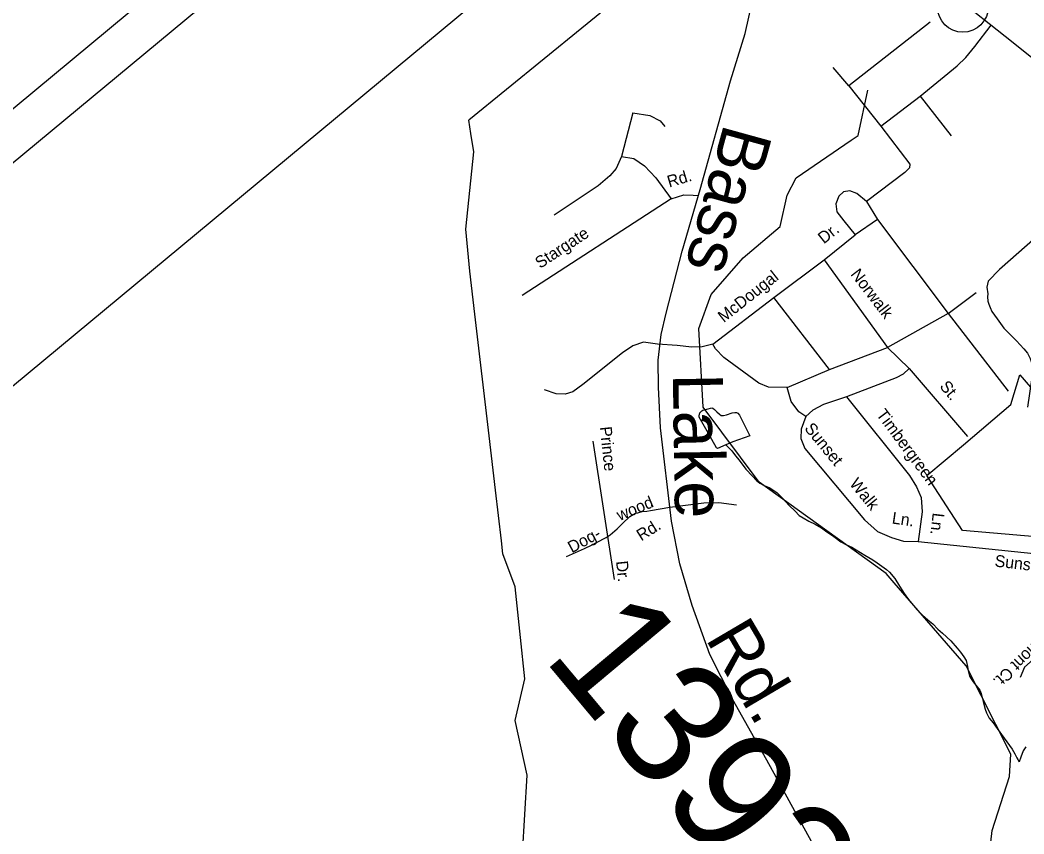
# Model space of a CAD drawing. Extents: x 2054826 to 2060231, y 685508 to 690809.
# Drawn here: x 2058521.5 to 2058702.3, y 689675 to 689821.4 of the extents above; entities that cross this region are included whole.
import ezdxf

# ---------------------------------------------------------------- set-up
doc = ezdxf.new("R2010")
doc.units = 0
for name, color, linetype in [('Default', 7, 'Continuous'), ('Old_Level_10', 7, 'Continuous'), ('Old_Level_11', 7, 'Continuous'), ('Old_Level_32', 7, 'Continuous'), ('Old_Level_35', 7, 'Continuous'), ('Old_Level_48', 7, 'Continuous'), ('Old_Level_49', 7, 'Continuous'), ('Old_Level_56', 7, 'Continuous'), ('Old_Level_59', 7, 'Continuous'), ('Old_Level_62', 7, 'Continuous'), ('Old_Level_8', 7, 'Continuous'), ('Sheet Title CELL', 7, 'Continuous')]:
    doc.layers.add(name, color=color, linetype=linetype)

msp = doc.modelspace()

# ---------------------------------------------------------------- linework, layer by layer
at = {"layer": 'Default'}
msp.add_lwpolyline([(2058776.37, 689968.05), (2059134.67, 689535.97), (2058721.62, 689193.45), (2058363.32, 689625.52)], close=True, dxfattribs=at)
msp.add_circle((2058691.27, 689823.81), 4.59, dxfattribs=at)
at = {"layer": 'Old_Level_32'}
for points in [[(2058898.06, 689750.93), (2058894.95, 689750.93), (2058888.19, 689750.36), (2058876.56, 689749.59), (2058861.91, 689747.84), (2058857.42, 689747.89), (2058845.09, 689749.43), (2058833.63, 689751.66), (2058828.28, 689753), (2058821.63, 689755.93), (2058816.8, 689757.3), (2058812.24, 689757.5), (2058808.13, 689757.14), (2058797.44, 689755.69), (2058792.44, 689755.38), (2058787.43, 689756.01), (2058779.61, 689758.56), (2058771.71, 689762.05), (2058763.67, 689767.02), (2058755.45, 689773.25), (2058734.54, 689789.73), (2058719.88, 689801.66), (2058700.32, 689817.33), (2058689.1, 689826.26)], [(2058679.59, 689634.33), (2058678.7, 689638.67), (2058676.93, 689646.07), (2058675.26, 689651.03), (2058672.43, 689657.49), (2058665.7, 689670.57), (2058655.97, 689688.24), (2058649.78, 689699.24), (2058645.72, 689707.22), (2058642.52, 689716.04), (2058640.32, 689723.55), (2058638.82, 689731.26), (2058636.85, 689748.06), (2058636.51, 689755.34), (2058636.4, 689760.19), (2058636.96, 689764.8), (2058637.85, 689768.69), (2058640.76, 689779.82), (2058643.98, 689790.93), (2058649.46, 689810.49), (2058652.07, 689818.96), (2058653.3, 689824.33)]]:
    msp.add_lwpolyline(points, dxfattribs=at)
at = {"layer": 'Old_Level_35'}
for p, q in [((2058685.41, 689821.03), (2058670.75, 689809.58)), ((2058670.75, 689809.58), (2058667.91, 689812.85)), ((2058670.75, 689809.58), (2058676.53, 689802.3)), ((2058676.53, 689802.3), (2058683.61, 689807.72)), ((2058683.61, 689807.72), (2058689.19, 689800.57)), ((2058631.88, 689804.7), (2058629.81, 689796.88)), ((2058638.75, 689789.24), (2058611.92, 689771.82)), ((2058673.94, 689788.73), (2058675.91, 689785.53)), ((2058675.91, 689785.53), (2058671.87, 689782.76)), ((2058675.91, 689785.53), (2058688.65, 689768.6)), ((2058666.29, 689778.29), (2058671.87, 689782.76)), ((2058657.22, 689771.51), (2058666.29, 689778.29)), ((2058666.29, 689778.29), (2058677.72, 689762.48)), ((2058688.65, 689768.6), (2058693.67, 689772.39)), ((2058646.29, 689763.08), (2058657.22, 689771.51)), ((2058667.25, 689758.55), (2058657.22, 689771.51)), ((2058688.65, 689768.6), (2058677.72, 689762.48)), ((2058688.65, 689768.6), (2058699.42, 689754.64)), ((2058667.25, 689758.55), (2058677.72, 689762.48)), ((2058677.72, 689762.48), (2058681.6, 689758.71)), ((2058659.65, 689755.32), (2058667.25, 689758.55)), ((2058681.6, 689758.71), (2058692.11, 689746.5)), ((2058624.64, 689745.66), (2058628.52, 689720.74))]:
    msp.add_line(p, q, dxfattribs=at)
for points in [[(2058683.61, 689807.72), (2058690.26, 689813.18), (2058691.82, 689814.69), (2058693.43, 689816.63), (2058696.35, 689820.49)], [(2058631.88, 689804.7), (2058634.93, 689804.21), (2058636.8, 689803.25), (2058637.64, 689802.24)], [(2058676.53, 689802.3), (2058681.75, 689795.46), (2058681.69, 689794.81), (2058680.85, 689794), (2058673.94, 689788.73)], [(2058723.29, 689798.89), (2058697.86, 689776.5), (2058695.82, 689774.42), (2058695.59, 689773.35), (2058695.74, 689772.12), (2058695.73, 689771.61), (2058695.78, 689770.82), (2058695.96, 689770.29), (2058696.21, 689769.66), (2058696.51, 689768.98), (2058697.42, 689767.63), (2058698.67, 689765.97), (2058700.92, 689763.69), (2058702.24, 689762.25), (2058702.89, 689761.44), (2058703.39, 689760.51), (2058703.63, 689759.79), (2058703.72, 689759.27), (2058703.71, 689758.76), (2058703.66, 689757.89), (2058703.62, 689756.69), (2058702.94, 689751.73)], [(2058629.81, 689796.88), (2058628.83, 689794.71), (2058627.7, 689793.36), (2058625.59, 689791.6), (2058617.69, 689786.32)], [(2058629.81, 689796.88), (2058632.04, 689796.47), (2058633.94, 689795.15), (2058635.99, 689793.02), (2058638.75, 689789.24)], [(2058638.75, 689789.24), (2058641.06, 689789.97), (2058642.71, 689789.9), (2058643.66, 689789.81)], [(2058673.94, 689788.73), (2058672.2, 689790.2), (2058670.92, 689790.65), (2058669.81, 689790.52), (2058668.97, 689789.72), (2058668.41, 689788.34), (2058668.61, 689786.89), (2058669.84, 689785.3), (2058671.87, 689782.76)], [(2058636.28, 689763.09), (2058633.76, 689763.44), (2058631.88, 689762.78), (2058630.01, 689761.51), (2058622.85, 689755.83), (2058621.03, 689754.51), (2058619.67, 689754.08), (2058618.08, 689754.16), (2058615.95, 689754.9)], [(2058646.29, 689763.08), (2058644.37, 689762.59), (2058642.5, 689762.53), (2058639.83, 689762.83), (2058636.28, 689763.09)], [(2058659.65, 689755.32), (2058656.27, 689755.38), (2058654.57, 689756.08), (2058648.22, 689760.66), (2058646.77, 689762.27), (2058646.29, 689763.08)], [(2058681.6, 689758.71), (2058680.52, 689757.7), (2058679.25, 689757.05), (2058670.32, 689753.61)], [(2058663.03, 689750.07), (2058661.73, 689750.9), (2058660.36, 689752.79), (2058659.65, 689755.32)], [(2058670.32, 689753.61), (2058666.19, 689752.21), (2058664.29, 689751.23), (2058663.03, 689750.07)], [(2058670.32, 689753.61), (2058681.64, 689739.46), (2058682.94, 689737.42), (2058683.76, 689735.48), (2058683.97, 689732.93), (2058683.23, 689727.61)], [(2058663.03, 689750.07), (2058662.16, 689747.78), (2058662.13, 689746.13), (2058662.84, 689744.31), (2058673.57, 689731.48), (2058675.91, 689729.41), (2058678.45, 689728.3), (2058680.6, 689727.67), (2058683.23, 689727.61)], [(2058638.53, 689733.77), (2058644.65, 689734.54), (2058647.34, 689734.57), (2058650.5, 689734.18)], [(2058619.92, 689724.87), (2058623.17, 689726.33), (2058624.54, 689727.01), (2058625.32, 689727.38), (2058627.08, 689728.3), (2058627.78, 689728.78), (2058629.06, 689729.89), (2058629.58, 689730.38), (2058629.99, 689730.8), (2058631.29, 689732.09), (2058632.32, 689732.67), (2058632.75, 689732.76), (2058633.51, 689732.96), (2058634.35, 689733.05), (2058635.01, 689733.16), (2058638.53, 689733.77)], [(2058683.23, 689727.61), (2058726, 689723.14), (2058728.26, 689722.61)], [(2058716.32, 689703.58), (2058714.03, 689706.49), (2058711.72, 689708.37), (2058709.52, 689708.73), (2058707.14, 689708.35), (2058704.45, 689706.83), (2058702.37, 689704.94), (2058701.56, 689703.1)]]:
    msp.add_lwpolyline(points, dxfattribs=at)
at = {"layer": 'Old_Level_48'}
msp.add_lwpolyline([(2058701.55, 689757.6), (2058712.59, 689744.8), (2058722.56, 689728.12), (2058721.2, 689726.98), (2058691.22, 689729.57), (2058684.79, 689739.44), (2058691.41, 689744.98), (2058699.9, 689752.24), (2058701.55, 689757.6)], dxfattribs=at)
at = {"layer": 'Old_Level_49'}
msp.add_lwpolyline([(2058701.55, 689757.6), (2058712.59, 689744.8), (2058722.56, 689728.12), (2058721.2, 689726.98), (2058691.22, 689729.57), (2058684.79, 689739.44), (2058691.41, 689744.98), (2058699.9, 689752.24), (2058701.55, 689757.6)], dxfattribs=at)
at = {"layer": 'Old_Level_56'}
for p, q in [((2058641.86, 689835.6), (2058602.32, 689803.39)), ((2058608.09, 689727.72), (2058608.19, 689727.71))]:
    msp.add_line(p, q, dxfattribs=at)
at = {"layer": 'Old_Level_59'}
for p, q in [((2058602.7, 689801.01), (2058602.32, 689803.39)), ((2058605.98, 689746.62), (2058603.42, 689768.48)), ((2058607.13, 689736.8), (2058605.98, 689746.62)), ((2058608.19, 689727.71), (2058607.13, 689736.8))]:
    msp.add_line(p, q, dxfattribs=at)
for points in [[(2058671.18, 689799.79), (2058672.44, 689800.66), (2058674.14, 689808.77)], [(2058603.42, 689768.48), (2058602.51, 689776.23), (2058601.8, 689783.77), (2058603.22, 689797.67), (2058602.7, 689801.01)], [(2058678.93, 689720.14), (2058677.49, 689721.8), (2058654.58, 689738.26), (2058644.55, 689751.78), (2058643.73, 689765.92), (2058645.95, 689772.02), (2058651.72, 689778.62), (2058658.41, 689784.25), (2058659.62, 689789.89), (2058661.24, 689792.99), (2058671.18, 689799.79)], [(2058611.64, 689710.31), (2058610.66, 689719.41), (2058608.47, 689725.38), (2058608.19, 689727.71)], [(2058694.42, 689639.99), (2058694.37, 689648.3), (2058695.89, 689652.02), (2058696.85, 689659.18), (2058695.83, 689669.3), (2058696.54, 689675.57), (2058699.69, 689685.28), (2058699.88, 689689.3), (2058691.88, 689705.23), (2058678.93, 689720.14)], [(2058617.62, 689621.3), (2058618.34, 689631.82), (2058610.12, 689651.43), (2058610.36, 689665.44), (2058612.01, 689671.39), (2058612.82, 689685.54), (2058610.66, 689695.39), (2058612.43, 689702.89), (2058611.64, 689710.31)]]:
    msp.add_lwpolyline(points, dxfattribs=at)
at = {"layer": 'Old_Level_62'}
for points in [[(2058648.62, 689744.95), (2058647.12, 689744.29), (2058646.91, 689744.45), (2058645.27, 689747.41), (2058643.79, 689749.98), (2058643.81, 689750.17), (2058643.95, 689750.71), (2058644.3, 689751.09), (2058644.46, 689751.21), (2058645.02, 689751.35), (2058645.16, 689751.39)], [(2058645.16, 689751.39), (2058646.06, 689751.64), (2058646.29, 689751.56), (2058646.55, 689751.36), (2058647.01, 689750.9), (2058647.44, 689750.5), (2058647.79, 689750.28), (2058648.16, 689750.24), (2058648.72, 689750.38), (2058649.72, 689750.72), (2058650.23, 689750.8), (2058650.5, 689750.79), (2058650.77, 689750.67), (2058651.07, 689750.32), (2058652.91, 689746.61), (2058649.86, 689745.49), (2058648.62, 689744.95)], [(2058648.62, 689744.95), (2058649.68, 689743.88), (2058650.34, 689742.99), (2058651.01, 689742.2), (2058652.2, 689740.58), (2058653.42, 689739.32), (2058654.15, 689738.56), (2058654.7, 689738.1), (2058655.5, 689737.66), (2058656.39, 689737.3), (2058657.09, 689736.87), (2058657.82, 689736.31), (2058658.72, 689735.45), (2058660.03, 689734.08), (2058661.09, 689733.03), (2058661.81, 689732.27), (2058662.51, 689731.84), (2058663.52, 689731.24), (2058664.67, 689730.68), (2058665.81, 689730.04), (2058666.81, 689729.34), (2058668.03, 689728.5), (2058669.28, 689727.51), (2058670.34, 689726.97), (2058671.27, 689726.56), (2058672.07, 689726.11), (2058673.65, 689725.14), (2058675.04, 689724.28), (2058675.87, 689723.72), (2058676.7, 689723.13), (2058677.52, 689722.56), (2058678.08, 689722.09), (2058679.04, 689720.93), (2058679.89, 689719.54), (2058680.7, 689718.25), (2058681.48, 689717.13), (2058682.98, 689715.35), (2058684.01, 689714.32), (2058684.99, 689713.46), (2058685.85, 689712.75), (2058686.79, 689711.83), (2058687.59, 689711.07), (2058689.08, 689709.69), (2058690.26, 689708.39), (2058690.85, 689707.69), (2058691.47, 689706.85), (2058691.87, 689706.17), (2058692.1, 689705.09), (2058692.22, 689704.34), (2058692.45, 689703.36), (2058692.79, 689702.86), (2058693.15, 689702.32), (2058694.3, 689700.84), (2058694.58, 689700.21), (2058694.92, 689698.8), (2058695.31, 689697.43), (2058695.52, 689696.76), (2058696, 689695.79), (2058696.7, 689694.96), (2058697.45, 689693.96), (2058699.17, 689691.51), (2058700.12, 689690.19), (2058700.6, 689689.4), (2058700.99, 689688.63), (2058701.15, 689688.35), (2058701.39, 689687.95)], [(2058702.61, 689690.66), (2058702.12, 689689.91), (2058701.7, 689688.8), (2058701.39, 689687.95)]]:
    msp.add_lwpolyline(points, dxfattribs=at)
at = {"layer": 'Sheet Title CELL'}
for p, q in [((2057602.7, 689044.61), (2058780.44, 690021.25)), ((2057821.1, 689215.97), (2058785.23, 690015.48))]:
    msp.add_line(p, q, dxfattribs=at)

# ---------------------------------------------------------------- texts
at = {"layer": 'Old_Level_10'}
for s, height, rotation, p in [('Rd.', 2.133, 16.608, (2058638.41, 689791.26)), ('Stargate', 2.133, 33.3318, (2058615.16, 689776.61)), ('Dr.', 2.133, 38.3572, (2058666.24, 689781.04)), ('McDougal', 2.133, 38.3572, (2058648.22, 689766.88)), ('Norwalk', 2.133, 307.4188, (2058670.96, 689775.65)), ('St.', 2.133, 309.6534, (2058686.97, 689755.45)), ('Timbergreen', 2.1325, 306.7253, (2058675.58, 689750.43)), ('Sunset', 2.133, 309.1972, (2058662.64, 689747.88)), ('Prince', 2.133, 275.9796, (2058625.91, 689748.18)), ('Walk', 2.133, 309.1972, (2058670.75, 689737.92)), ('wood', 2.133, 22.6269, (2058629.49, 689731.25)), ('Ln.', 2.133, 351.8366, (2058678.41, 689730.83)), ('Ln.', 2.133, 263.4528, (2058685.86, 689732.82)), ('Rd.', 2.133, 32.1009, (2058633.37, 689727.59)), ('Dog-', 2.133, 28.4869, (2058620.88, 689725.44)), ('Sunset', 2.133, 353.3381, (2058696.92, 689723.09)), ('Dr.', 2.133, 275.9796, (2058628.83, 689724.01)), ('Oakmont Ct.', 2.1325, 223.0852, (2058708.19, 689713.58))]:
    msp.add_text(s, height=height, rotation=rotation, dxfattribs=at).set_placement(p)
at = {"layer": 'Old_Level_11'}
for s, rotation, p in [('Bass', 254.5695, (2058648.35, 689802.99)), ('Lake', 270.9358, (2058639.05, 689757.77)), ('Rd.', 300.4412, (2058644.83, 689710.13))]:
    msp.add_text(s, height=8.997, rotation=rotation, dxfattribs=at).set_placement(p)
at = {"layer": 'Old_Level_8'}
msp.add_text('1393', height=21.964, rotation=309.9093, dxfattribs=at).set_placement((2058615.48, 689706.71))

doc.saveas('drawing.dxf')
